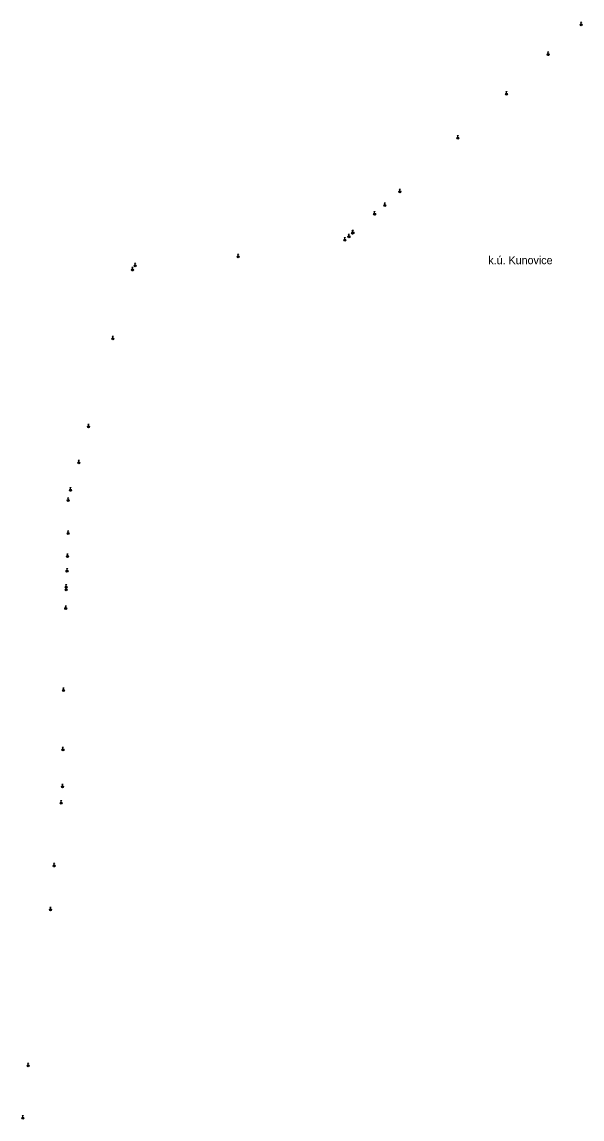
# Model space of a CAD drawing. Extents: x -540161 to -537510, y -1183993 to -1180459.
# Drawn here: x -540028 to -539818.1, y -1183530.4 to -1183119.2 of the extents above; entities that cross this region are included whole.
import ezdxf

# ---------------------------------------------------------------- set-up
doc = ezdxf.new("R2010")
doc.units = 0
doc.layers.add('NÁZEV_K_Ú', color=7, linetype='Continuous')
doc.layers.add('ZN_BP', color=7, linetype='Continuous')

msp = doc.modelspace()

# ---------------------------------------------------------------- linework, layer by layer
at = {"layer": 'ZN_BP'}
for p, q in [((-539818.745, -1183120.554), (-539818.216, -1183120.026)), ((-539818.216, -1183120.558), (-539818.745, -1183120.026)), ((-539818.48, -1183119.915), (-539818.48, -1183119.165)), ((-539831.085, -1183131.684), (-539830.556, -1183131.156)), ((-539830.556, -1183131.688), (-539831.085, -1183131.156)), ((-539830.82, -1183131.045), (-539830.82, -1183130.295)), ((-539846.43, -1183145.855), (-539846.43, -1183145.105)), ((-539846.695, -1183146.494), (-539846.166, -1183145.966)), ((-539846.166, -1183146.498), (-539846.695, -1183145.966)), ((-539864.63, -1183162.355), (-539864.63, -1183161.605)), ((-539864.895, -1183162.994), (-539864.366, -1183162.466)), ((-539864.366, -1183162.998), (-539864.895, -1183162.466)), ((-539886.625, -1183183.064), (-539886.096, -1183182.536)), ((-539886.096, -1183183.068), (-539886.625, -1183182.536)), ((-539886.36, -1183182.425), (-539886.36, -1183181.675)), ((-539895.82, -1183190.895), (-539895.82, -1183190.145)), ((-539892.315, -1183188.224), (-539891.786, -1183187.696)), ((-539891.786, -1183188.228), (-539892.315, -1183187.696)), ((-539892.05, -1183187.585), (-539892.05, -1183186.835)), ((-539896.085, -1183191.534), (-539895.556, -1183191.006)), ((-539895.556, -1183191.538), (-539896.085, -1183191.006)), ((-539905.44, -1183199.285), (-539905.44, -1183198.535)), ((-539904.345, -1183198.654), (-539903.816, -1183198.126)), ((-539903.816, -1183198.658), (-539904.345, -1183198.126)), ((-539904.205, -1183198.484), (-539903.676, -1183197.956)), ((-539903.676, -1183198.488), (-539904.205, -1183197.956)), ((-539904.08, -1183198.015), (-539904.08, -1183197.265)), ((-539903.94, -1183197.845), (-539903.94, -1183197.095)), ((-539907.215, -1183201.274), (-539906.686, -1183200.746)), ((-539906.686, -1183201.278), (-539907.215, -1183200.746)), ((-539906.95, -1183200.635), (-539906.95, -1183199.885)), ((-539905.705, -1183199.924), (-539905.176, -1183199.396)), ((-539905.176, -1183199.928), (-539905.705, -1183199.396)), ((-539947.245, -1183207.504), (-539946.716, -1183206.976)), ((-539946.716, -1183207.508), (-539947.245, -1183206.976)), ((-539946.98, -1183206.865), (-539946.98, -1183206.115)), ((-539986.57, -1183211.765), (-539986.57, -1183211.015)), ((-539985.855, -1183210.854), (-539985.326, -1183210.326)), ((-539985.326, -1183210.858), (-539985.855, -1183210.326)), ((-539985.59, -1183210.215), (-539985.59, -1183209.465)), ((-539986.835, -1183212.404), (-539986.306, -1183211.876)), ((-539986.306, -1183212.408), (-539986.835, -1183211.876)), ((-539994.215, -1183238.194), (-539993.686, -1183237.666)), ((-539993.686, -1183238.198), (-539994.215, -1183237.666)), ((-539993.95, -1183237.555), (-539993.95, -1183236.805)), ((-540003.335, -1183271.154), (-540002.806, -1183270.626)), ((-540002.806, -1183271.158), (-540003.335, -1183270.626)), ((-540003.07, -1183270.515), (-540003.07, -1183269.765)), ((-540006.905, -1183284.724), (-540006.376, -1183284.196)), ((-540006.376, -1183284.728), (-540006.905, -1183284.196)), ((-540006.64, -1183284.085), (-540006.64, -1183283.335)), ((-540009.75, -1183294.365), (-540009.75, -1183293.615)), ((-540010.66, -1183298.135), (-540010.66, -1183297.385)), ((-540010.015, -1183295.004), (-540009.486, -1183294.476)), ((-540009.486, -1183295.008), (-540010.015, -1183294.476)), ((-540010.925, -1183298.774), (-540010.396, -1183298.246)), ((-540010.396, -1183298.778), (-540010.925, -1183298.246)), ((-540010.68, -1183310.575), (-540010.68, -1183309.825)), ((-540010.945, -1183311.214), (-540010.416, -1183310.686)), ((-540010.416, -1183311.218), (-540010.945, -1183310.686)), ((-540010.89, -1183319.115), (-540010.89, -1183318.365)), ((-540011.155, -1183319.754), (-540010.626, -1183319.226)), ((-540010.626, -1183319.758), (-540011.155, -1183319.226)), ((-540011.365, -1183325.324), (-540010.836, -1183324.796)), ((-540010.836, -1183325.328), (-540011.365, -1183324.796)), ((-540011.1, -1183324.685), (-540011.1, -1183323.935)), ((-540011.43, -1183330.665), (-540011.43, -1183329.915)), ((-540011.695, -1183331.304), (-540011.166, -1183330.776)), ((-540011.166, -1183331.308), (-540011.695, -1183330.776)), ((-540011.685, -1183332.324), (-540011.156, -1183331.796)), ((-540011.156, -1183332.328), (-540011.685, -1183331.796)), ((-540011.42, -1183331.685), (-540011.42, -1183330.935)), ((-540011.855, -1183339.304), (-540011.326, -1183338.776)), ((-540011.326, -1183339.308), (-540011.855, -1183338.776)), ((-540011.59, -1183338.665), (-540011.59, -1183337.915)), ((-540012.695, -1183370.084), (-540012.166, -1183369.556)), ((-540012.166, -1183370.088), (-540012.695, -1183369.556)), ((-540012.43, -1183369.445), (-540012.43, -1183368.695)), ((-540012.875, -1183392.324), (-540012.346, -1183391.796)), ((-540012.346, -1183392.328), (-540012.875, -1183391.796)), ((-540012.61, -1183391.685), (-540012.61, -1183390.935)), ((-540012.81, -1183405.465), (-540012.81, -1183404.715)), ((-540013.075, -1183406.104), (-540012.546, -1183405.576)), ((-540012.546, -1183406.108), (-540013.075, -1183405.576)), ((-540013.525, -1183412.244), (-540012.996, -1183411.716)), ((-540012.996, -1183412.248), (-540013.525, -1183411.716)), ((-540013.26, -1183411.605), (-540013.26, -1183410.855)), ((-540016.145, -1183435.834), (-540015.616, -1183435.306)), ((-540015.616, -1183435.838), (-540016.145, -1183435.306)), ((-540015.88, -1183435.195), (-540015.88, -1183434.445)), ((-540017.575, -1183452.214), (-540017.046, -1183451.686)), ((-540017.046, -1183452.218), (-540017.575, -1183451.686)), ((-540017.31, -1183451.575), (-540017.31, -1183450.825)), ((-540025.945, -1183510.744), (-540025.416, -1183510.216)), ((-540025.416, -1183510.748), (-540025.945, -1183510.216)), ((-540025.68, -1183510.105), (-540025.68, -1183509.355)), ((-540027.875, -1183530.324), (-540027.346, -1183529.796)), ((-540027.346, -1183530.328), (-540027.875, -1183529.796)), ((-540027.61, -1183529.685), (-540027.61, -1183528.935))]:
    msp.add_line(p, q, dxfattribs=at)
for points in [[(-539818.605, -1183119.415), (-539818.48, -1183119.165), (-539818.355, -1183119.415)], [(-539830.945, -1183130.545), (-539830.82, -1183130.295), (-539830.695, -1183130.545)], [(-539846.555, -1183145.355), (-539846.43, -1183145.105), (-539846.305, -1183145.355)], [(-539864.755, -1183161.855), (-539864.63, -1183161.605), (-539864.505, -1183161.855)], [(-539886.485, -1183181.925), (-539886.36, -1183181.675), (-539886.235, -1183181.925)], [(-539895.945, -1183190.395), (-539895.82, -1183190.145), (-539895.695, -1183190.395)], [(-539892.175, -1183187.085), (-539892.05, -1183186.835), (-539891.925, -1183187.085)], [(-539905.565, -1183198.785), (-539905.44, -1183198.535), (-539905.315, -1183198.785)], [(-539904.205, -1183197.515), (-539904.08, -1183197.265), (-539903.955, -1183197.515)], [(-539904.065, -1183197.345), (-539903.94, -1183197.095), (-539903.815, -1183197.345)], [(-539907.075, -1183200.135), (-539906.95, -1183199.885), (-539906.825, -1183200.135)], [(-539947.105, -1183206.365), (-539946.98, -1183206.115), (-539946.855, -1183206.365)], [(-539986.695, -1183211.265), (-539986.57, -1183211.015), (-539986.445, -1183211.265)], [(-539985.715, -1183209.715), (-539985.59, -1183209.465), (-539985.465, -1183209.715)], [(-539994.075, -1183237.055), (-539993.95, -1183236.805), (-539993.825, -1183237.055)], [(-540003.195, -1183270.015), (-540003.07, -1183269.765), (-540002.945, -1183270.015)], [(-540006.765, -1183283.585), (-540006.64, -1183283.335), (-540006.515, -1183283.585)], [(-540009.875, -1183293.865), (-540009.75, -1183293.615), (-540009.625, -1183293.865)], [(-540010.785, -1183297.635), (-540010.66, -1183297.385), (-540010.535, -1183297.635)], [(-540010.805, -1183310.075), (-540010.68, -1183309.825), (-540010.555, -1183310.075)], [(-540011.015, -1183318.615), (-540010.89, -1183318.365), (-540010.765, -1183318.615)], [(-540011.225, -1183324.185), (-540011.1, -1183323.935), (-540010.975, -1183324.185)], [(-540011.555, -1183330.165), (-540011.43, -1183329.915), (-540011.305, -1183330.165)], [(-540011.545, -1183331.185), (-540011.42, -1183330.935), (-540011.295, -1183331.185)], [(-540011.715, -1183338.165), (-540011.59, -1183337.915), (-540011.465, -1183338.165)], [(-540012.555, -1183368.945), (-540012.43, -1183368.695), (-540012.305, -1183368.945)], [(-540012.735, -1183391.185), (-540012.61, -1183390.935), (-540012.485, -1183391.185)], [(-540012.935, -1183404.965), (-540012.81, -1183404.715), (-540012.685, -1183404.965)], [(-540013.385, -1183411.105), (-540013.26, -1183410.855), (-540013.135, -1183411.105)], [(-540016.005, -1183434.695), (-540015.88, -1183434.445), (-540015.755, -1183434.695)], [(-540017.435, -1183451.075), (-540017.31, -1183450.825), (-540017.185, -1183451.075)], [(-540025.805, -1183509.605), (-540025.68, -1183509.355), (-540025.555, -1183509.605)], [(-540027.735, -1183529.185), (-540027.61, -1183528.935), (-540027.485, -1183529.185)]]:
    msp.add_lwpolyline(points, dxfattribs=at)
for centre in [(-539818.48, -1183120.29), (-539830.82, -1183131.42), (-539846.43, -1183146.23), (-539864.63, -1183162.73), (-539886.36, -1183182.8), (-539892.05, -1183187.96), (-539895.82, -1183191.27), (-539904.08, -1183198.39), (-539903.94, -1183198.22), (-539906.95, -1183201.01), (-539905.44, -1183199.66), (-539946.98, -1183207.24), (-539985.59, -1183210.59), (-539986.57, -1183212.14), (-539993.95, -1183237.93), (-540003.07, -1183270.89), (-540006.64, -1183284.46), (-540009.75, -1183294.74), (-540010.66, -1183298.51), (-540010.68, -1183310.95), (-540010.89, -1183319.49), (-540011.1, -1183325.06), (-540011.43, -1183331.04), (-540011.42, -1183332.06), (-540011.59, -1183339.04), (-540012.43, -1183369.82), (-540012.61, -1183392.06), (-540012.81, -1183405.84), (-540013.26, -1183411.98), (-540015.88, -1183435.57), (-540017.31, -1183451.95), (-540025.68, -1183510.48), (-540027.61, -1183530.06)]:
    msp.add_circle(centre, 0.375, dxfattribs=at)

# ---------------------------------------------------------------- texts
at = {"layer": 'NÁZEV_K_Ú'}
msp.add_text('k.ú. Kunovice', height=3, dxfattribs=at).set_placement((-539853.24, -1183209.98))

doc.saveas('drawing.dxf')
